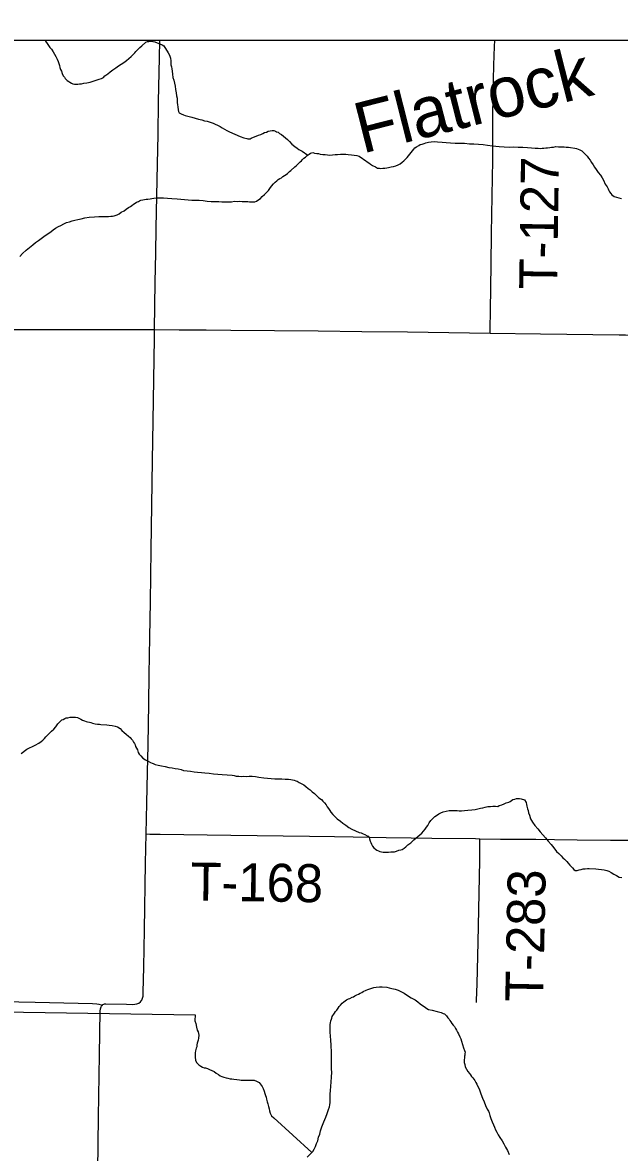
# Model space of a CAD drawing. Extents: x 2.1 to 73.9, y 4 to 26.
# Drawn here: x 44.468 to 44.915, y 18.709 to 19.554 of the extents above; entities that cross this region are included whole.
import ezdxf

# ---------------------------------------------------------------- set-up
doc = ezdxf.new("R2010")
doc.units = 0
for name, color, linetype in [('GM_X_County_Road', 7, 'Continuous'), ('GM_X_Minor_Lake_Text', 7, 'Continuous'), ('GM_X_Minor_River', 7, 'Continuous'), ('GM_X_Township_Road', 7, 'Continuous'), ('GM_X_Township_Road_Text', 7, 'Continuous'), ('SH_Text', 7, 'Continuous')]:
    doc.layers.add(name, color=color, linetype=linetype)

msp = doc.modelspace()

# ---------------------------------------------------------------- linework, layer by layer
at = {"layer": 'GM_X_County_Road'}
for points in [[(44.56658, 19.3248), (44.56701, 19.36025), (44.56761, 19.382), (44.56786, 19.40064), (44.56881, 19.44881), (44.56918, 19.47056), (44.56955, 19.49542), (44.57019, 19.52805), (44.57042, 19.54109)], [(44.56027, 18.94717), (44.56073, 18.97025), (44.56132, 18.99356), (44.56168, 19.01375), (44.56227, 19.04483), (44.56263, 19.06658), (44.56308, 19.09455), (44.56349, 19.12096), (44.56401, 19.15981), (44.56508, 19.22662), (44.56552, 19.25614), (44.56649, 19.3183), (44.56658, 19.3248)], [(44.55035, 18.81959), (44.55191, 18.81972), (44.55342, 18.82004), (44.55483, 18.82066), (44.55606, 18.82159), (44.55661, 18.82219), (44.55699, 18.82282), (44.55761, 18.82425), (44.55794, 18.82577), (44.55816, 18.82887), (44.55848, 18.84751), (44.55903, 18.87548), (44.55984, 18.9252), (44.56027, 18.94717)], [(44.51978, 18.31658), (44.52008, 18.34537), (44.52022, 18.37179), (44.5205, 18.39354), (44.52092, 18.43238), (44.52118, 18.44792), (44.5214, 18.46967), (44.52162, 18.48832), (44.52216, 18.51628), (44.52264, 18.54269), (44.52329, 18.60795), (44.52346, 18.62815), (44.52406, 18.69497), (44.52455, 18.73537), (44.52534, 18.78198), (44.52599, 18.81463), (44.52616, 18.81619), (44.52655, 18.8177), (44.52684, 18.81833), (44.52751, 18.81903)], [(44.52751, 18.81903), (44.52792, 18.81948), (44.5286, 18.81981), (44.5291, 18.81993), (44.53014, 18.82004), (44.54568, 18.81967), (44.55035, 18.81959)]]:
    msp.add_lwpolyline(points, dxfattribs=at)
at = {"layer": 'GM_X_Minor_River'}
for points in [[(44.48463, 19.54109), (44.48497, 19.54049), (44.48608, 19.53895), (44.48719, 19.5374), (44.4881, 19.53586), (44.4894, 19.5345), (44.49069, 19.53257), (44.4916, 19.53084), (44.4927, 19.52911), (44.49361, 19.52719), (44.49433, 19.52546), (44.49505, 19.52393), (44.4954, 19.5224), (44.49574, 19.52088), (44.49628, 19.51934), (44.49682, 19.518), (44.49754, 19.51628), (44.49826, 19.51455), (44.49919, 19.51358), (44.49974, 19.51262), (44.50122, 19.51107), (44.50441, 19.5091), (44.50535, 19.50869), (44.50668, 19.50847), (44.50763, 19.50845), (44.50915, 19.50842), (44.51029, 19.50858), (44.51182, 19.50874), (44.51353, 19.50908), (44.51601, 19.5094), (44.5185, 19.50992), (44.5206, 19.51063), (44.5229, 19.51134), (44.52501, 19.51205), (44.52692, 19.51258), (44.52827, 19.51331), (44.52944, 19.51461), (44.53156, 19.51608), (44.53331, 19.51756), (44.53544, 19.51922), (44.53756, 19.52069), (44.53969, 19.52216), (44.54162, 19.52345), (44.54355, 19.52473), (44.54548, 19.52621), (44.54742, 19.52769), (44.54897, 19.52917), (44.55033, 19.53047), (44.5517, 19.53196), (44.55267, 19.53289), (44.55403, 19.53437), (44.55559, 19.53586), (44.55695, 19.53716), (44.56005, 19.53975), (44.56139, 19.54028), (44.56235, 19.54045), (44.5633, 19.54062), (44.56444, 19.5406), (44.56539, 19.54039), (44.56671, 19.53998), (44.56859, 19.53936), (44.57048, 19.53856), (44.57217, 19.53776), (44.57348, 19.53697)], [(44.57348, 19.53697), (44.57679, 19.53196), (44.5777, 19.53004), (44.57841, 19.52794), (44.57874, 19.52584), (44.57871, 19.52432), (44.57886, 19.5228), (44.57921, 19.52146), (44.57955, 19.51975), (44.57971, 19.51803), (44.58004, 19.51594), (44.58036, 19.51346), (44.58107, 19.51136), (44.58141, 19.50926), (44.58192, 19.50697), (44.58225, 19.50449), (44.58276, 19.50201), (44.58309, 19.49973), (44.58342, 19.49782), (44.58358, 19.49611), (44.58354, 19.49459), (44.58369, 19.49287), (44.58404, 19.49135), (44.58437, 19.48906), (44.58453, 19.48792), (44.58508, 19.48696), (44.58639, 19.48617), (44.58827, 19.48536), (44.5896, 19.48496), (44.59148, 19.48434), (44.59451, 19.48371), (44.59696, 19.48289), (44.59942, 19.48226), (44.60188, 19.48164), (44.60395, 19.48102), (44.60585, 19.4806), (44.60755, 19.48018), (44.60905, 19.47958), (44.61057, 19.47917), (44.61207, 19.47837), (44.61358, 19.47777), (44.61564, 19.47677), (44.61714, 19.47579), (44.61883, 19.4748), (44.62071, 19.47381), (44.62278, 19.47281), (44.63068, 19.46922), (44.63351, 19.4682), (44.63559, 19.46778), (44.63653, 19.46757), (44.63805, 19.46753), (44.63901, 19.46789), (44.64075, 19.4688), (44.64266, 19.46952), (44.64439, 19.47024), (44.64611, 19.47077), (44.64765, 19.47149), (44.649, 19.47222), (44.65034, 19.47257), (44.65168, 19.47311), (44.65302, 19.47346), (44.65473, 19.47361), (44.65587, 19.47359), (44.657, 19.47318), (44.65795, 19.47278), (44.65908, 19.47237), (44.6602, 19.47159), (44.66151, 19.47061), (44.663, 19.46944), (44.6645, 19.46827), (44.66618, 19.4669), (44.66767, 19.46553), (44.66933, 19.46341), (44.67157, 19.46165), (44.67325, 19.46047), (44.67456, 19.45949), (44.67569, 19.4589), (44.67701, 19.4583), (44.68136, 19.45534)], [(44.74901, 19.44813), (44.75036, 19.44886), (44.75191, 19.44996), (44.75326, 19.45107), (44.75443, 19.45219), (44.7556, 19.45349), (44.75658, 19.4548), (44.75775, 19.4561), (44.76068, 19.45964), (44.76147, 19.46076), (44.76263, 19.4615), (44.76436, 19.4626), (44.76532, 19.46314), (44.76685, 19.46349), (44.76839, 19.46403), (44.76973, 19.46437), (44.77164, 19.4649), (44.77355, 19.46524), (44.77583, 19.46538), (44.7783, 19.46532), (44.78191, 19.46505), (44.78475, 19.4648), (44.78817, 19.46453), (44.79158, 19.46426), (44.795, 19.46419), (44.79862, 19.46411), (44.80222, 19.46383), (44.80564, 19.46376), (44.80906, 19.46349), (44.81247, 19.46322), (44.81588, 19.46277), (44.81949, 19.46231), (44.82461, 19.46181), (44.8284, 19.46153), (44.83201, 19.46126), (44.83543, 19.46138), (44.83885, 19.4613), (44.84227, 19.46122), (44.84569, 19.46096), (44.84872, 19.4607), (44.85157, 19.46044), (44.85385, 19.46039), (44.85537, 19.46036), (44.85671, 19.46052), (44.85803, 19.46049), (44.85937, 19.46065), (44.8607, 19.46081), (44.86242, 19.46096), (44.86375, 19.46112), (44.86528, 19.46127), (44.86699, 19.46162), (44.86908, 19.46157), (44.87117, 19.46152), (44.87308, 19.46148), (44.87478, 19.46125), (44.87649, 19.46121), (44.87782, 19.46099), (44.88123, 19.46054), (44.88236, 19.46013), (44.88368, 19.45972), (44.885, 19.45912), (44.88632, 19.45852), (44.88743, 19.45755), (44.88873, 19.45619), (44.8904, 19.45444), (44.89151, 19.45309), (44.89262, 19.45154), (44.89372, 19.44981), (44.89482, 19.44808), (44.89592, 19.44634), (44.89721, 19.44441), (44.89868, 19.44229), (44.90034, 19.44016), (44.90163, 19.43824), (44.90273, 19.4365), (44.904, 19.43363), (44.90528, 19.43151), (44.90619, 19.42997), (44.90655, 19.42882), (44.9071, 19.42786), (44.90802, 19.42651), (44.90894, 19.42554), (44.91063, 19.42436), (44.91233, 19.42375), (44.91403, 19.42334), (44.91611, 19.42291)], [(44.57336, 19.42341), (44.57621, 19.42316), (44.57944, 19.42289), (44.58342, 19.42261), (44.59177, 19.42186), (44.59442, 19.42161), (44.59708, 19.42155), (44.59994, 19.42148), (44.60297, 19.42122), (44.606, 19.42078), (44.60904, 19.42052), (44.6117, 19.42046), (44.61474, 19.42058), (44.61702, 19.42034), (44.6193, 19.42029), (44.62177, 19.42023), (44.62424, 19.42036), (44.62634, 19.4207), (44.62862, 19.42065), (44.63053, 19.42079), (44.63223, 19.42056), (44.63375, 19.42053), (44.63528, 19.42069), (44.63641, 19.42047), (44.63774, 19.42044), (44.63907, 19.42041), (44.6404, 19.42038), (44.64154, 19.42035), (44.64288, 19.4207), (44.64462, 19.42199), (44.64578, 19.42292), (44.64714, 19.42422), (44.64889, 19.42589), (44.65045, 19.42737), (44.65181, 19.42886), (44.65299, 19.43035), (44.65416, 19.43203), (44.65553, 19.43371), (44.65689, 19.43501), (44.65806, 19.43612), (44.65922, 19.43705), (44.66038, 19.43778), (44.66153, 19.43833), (44.6625, 19.43925), (44.66385, 19.43998), (44.66501, 19.44072), (44.66598, 19.44145), (44.66753, 19.44294), (44.6685, 19.44387), (44.6716, 19.44645), (44.67257, 19.44738), (44.67393, 19.44849), (44.67471, 19.44942), (44.67549, 19.45036), (44.67646, 19.45109), (44.67743, 19.45202), (44.6784, 19.45295), (44.67956, 19.45368), (44.68092, 19.45498), (44.68228, 19.45609), (44.68344, 19.45682), (44.68515, 19.45716), (44.68629, 19.45676), (44.68799, 19.45653), (44.68932, 19.4565), (44.69045, 19.4561), (44.69254, 19.45586), (44.69424, 19.45563), (44.69614, 19.45559), (44.69785, 19.45536), (44.69975, 19.45551), (44.70166, 19.45565), (44.70356, 19.4558), (44.70566, 19.45594), (44.70775, 19.45609), (44.70965, 19.45604), (44.71155, 19.45581), (44.71401, 19.45557), (44.7161, 19.45533), (44.71799, 19.4551), (44.71969, 19.45449), (44.72082, 19.4537), (44.72194, 19.45292), (44.72325, 19.45213), (44.72437, 19.45115), (44.72568, 19.45036), (44.72699, 19.44939), (44.7283, 19.44841), (44.7298, 19.44742), (44.73187, 19.44643), (44.73356, 19.44563), (44.73507, 19.44541), (44.73602, 19.44538), (44.73736, 19.44554), (44.73888, 19.44551), (44.7404, 19.44567), (44.74174, 19.44602), (44.74365, 19.44654), (44.74556, 19.44688), (44.74709, 19.44722), (44.74901, 19.44813)], [(44.46572, 19.3795), (44.46785, 19.38154), (44.47058, 19.38413), (44.47309, 19.38617), (44.47542, 19.3882), (44.47755, 19.38987), (44.47967, 19.39134), (44.4818, 19.39281), (44.48373, 19.39428), (44.48914, 19.39815), (44.49069, 19.39925), (44.49243, 19.40073), (44.49474, 19.40182), (44.49647, 19.40273), (44.49859, 19.40382), (44.5007, 19.40473), (44.50281, 19.40544), (44.50492, 19.40615), (44.50682, 19.40649), (44.50912, 19.40701), (44.5116, 19.40771), (44.51447, 19.4084), (44.51752, 19.40891), (44.52171, 19.40919), (44.52476, 19.40931), (44.52742, 19.40944), (44.53008, 19.40938), (44.53217, 19.40933), (44.53389, 19.40949), (44.53522, 19.40965), (44.53636, 19.40981), (44.53848, 19.41071), (44.54001, 19.41125), (44.54156, 19.41254), (44.54387, 19.41363), (44.54541, 19.41473), (44.54696, 19.41603), (44.5485, 19.41694), (44.54966, 19.41768), (44.55082, 19.4186), (44.55198, 19.41933), (44.55314, 19.42007), (44.55448, 19.42061), (44.55544, 19.42115), (44.5564, 19.42151), (44.55793, 19.42186), (44.55908, 19.42202), (44.56022, 19.42238), (44.56155, 19.42235), (44.56327, 19.4225), (44.56461, 19.42285), (44.56613, 19.423), (44.56823, 19.42334), (44.5707, 19.42328), (44.57336, 19.42341)], [(44.46678, 19.00741), (44.47103, 19.01054), (44.47719, 19.01363), (44.47988, 19.01509), (44.48162, 19.01638), (44.48298, 19.01749), (44.48414, 19.01861), (44.48531, 19.01991), (44.48648, 19.02121), (44.48785, 19.0227), (44.4894, 19.02418), (44.49115, 19.02566), (44.49271, 19.02734), (44.49409, 19.02959), (44.49584, 19.03126), (44.4972, 19.03256), (44.49815, 19.03291), (44.49931, 19.03365), (44.50046, 19.034), (44.5016, 19.03417), (44.50332, 19.03451), (44.50542, 19.03465), (44.50732, 19.03461), (44.50902, 19.03438), (44.51034, 19.03359), (44.51128, 19.03319), (44.51259, 19.0324), (44.5141, 19.0318), (44.51542, 19.03139), (44.51636, 19.03117), (44.51788, 19.03076), (44.51882, 19.03055), (44.52014, 19.03014), (44.52222, 19.02971), (44.52393, 19.02948), (44.52545, 19.02926), (44.52639, 19.02905), (44.53076, 19.02876), (44.53266, 19.02872)], [(44.53266, 19.02872), (44.53474, 19.02848), (44.53701, 19.02786), (44.5389, 19.02725), (44.54077, 19.02607), (44.54207, 19.02471), (44.54375, 19.02315), (44.54543, 19.02178), (44.54711, 19.02042), (44.54823, 19.01944), (44.54915, 19.01847), (44.55008, 19.01731), (44.55081, 19.01596), (44.55155, 19.015), (44.55209, 19.01385), (44.55244, 19.0127), (44.55299, 19.01136), (44.55372, 19.0102), (44.55408, 19.00924), (44.55443, 19.0081), (44.55517, 19.00694), (44.55628, 19.00558), (44.55776, 19.00403), (44.55982, 19.00266), (44.56189, 19.00166), (44.56358, 19.00067), (44.56471, 19.00027), (44.56565, 18.99986), (44.56716, 18.99926), (44.56924, 18.99864), (44.5717, 18.99821), (44.57454, 18.99758), (44.57737, 18.99694), (44.57984, 18.9967), (44.58192, 18.99627), (44.58419, 18.99584), (44.58646, 18.99541), (44.58835, 18.9948), (44.591, 18.99436), (44.59347, 18.99411), (44.59612, 18.99367), (44.59877, 18.99342), (44.60162, 18.99317), (44.60428, 18.99292), (44.6075, 18.99266), (44.61072, 18.9922), (44.61395, 18.99194), (44.61717, 18.99168), (44.62458, 18.99113), (44.62609, 18.99091), (44.62779, 18.99049), (44.62969, 18.99045), (44.63178, 18.99021), (44.63349, 18.99036), (44.63558, 18.99031), (44.63749, 18.99046), (44.63977, 18.99041), (44.64204, 18.99017), (44.64469, 18.98973), (44.64849, 18.98926), (44.65114, 18.98901), (44.65399, 18.98876), (44.65664, 18.98851), (44.6593, 18.98845), (44.66177, 18.98839), (44.66443, 18.98815), (44.6669, 18.98809), (44.6686, 18.98786), (44.66993, 18.98764), (44.67107, 18.98743), (44.67239, 18.98702), (44.67333, 18.98662), (44.67483, 18.98582), (44.67634, 18.98503), (44.67821, 18.98385), (44.67989, 18.98267), (44.68157, 18.9813), (44.68307, 18.98013), (44.68456, 18.97877), (44.68624, 18.9774), (44.68792, 18.97603), (44.68959, 18.97428), (44.69146, 18.97291), (44.69257, 18.97175), (44.69369, 18.97058), (44.69498, 18.96903), (44.6959, 18.9675), (44.69682, 18.96614), (44.69774, 18.96479), (44.69866, 18.96344), (44.70014, 18.9617), (44.70163, 18.96015), (44.7033, 18.95859), (44.70573, 18.95664), (44.7076, 18.95527), (44.70966, 18.9537), (44.7119, 18.95213), (44.71415, 18.95075), (44.7198, 18.94834), (44.72131, 18.94793), (44.72263, 18.94733)], [(44.72263, 18.94733), (44.72394, 18.94673), (44.72563, 18.94574), (44.72658, 18.94553), (44.72713, 18.94457), (44.72748, 18.94342), (44.72802, 18.94189), (44.72856, 18.94074), (44.72892, 18.93959), (44.72983, 18.93805), (44.73076, 18.93689), (44.73188, 18.93592), (44.733, 18.93513), (44.73412, 18.93454), (44.73525, 18.93394), (44.73639, 18.93373), (44.73771, 18.93351), (44.73923, 18.93347), (44.74056, 18.93344), (44.74171, 18.93361), (44.74342, 18.93376), (44.74609, 18.93389), (44.74762, 18.93442), (44.74934, 18.93495), (44.75087, 18.9353), (44.75183, 18.93566), (44.75337, 18.93657), (44.75472, 18.93749), (44.75628, 18.93898), (44.75841, 18.94064), (44.76073, 18.94268), (44.76674, 18.94786), (44.76792, 18.94935), (44.76909, 18.95084), (44.77007, 18.95215), (44.77125, 18.95364), (44.77224, 18.95552), (44.77342, 18.9572), (44.77478, 18.95869), (44.77634, 18.96018), (44.77769, 18.9611), (44.77942, 18.9622), (44.78096, 18.96292), (44.78269, 18.96364), (44.78498, 18.96435), (44.78708, 18.96468), (44.78842, 18.96484), (44.78975, 18.96481), (44.79127, 18.96478), (44.79298, 18.96474), (44.79468, 18.96451), (44.79639, 18.96447), (44.79868, 18.9648), (44.80116, 18.96494), (44.80401, 18.96525), (44.80649, 18.96558), (44.80859, 18.96591), (44.8105, 18.96644), (44.81222, 18.96678), (44.81414, 18.9673), (44.81605, 18.96764), (44.81795, 18.96779), (44.81985, 18.96794), (44.82175, 18.96789), (44.82346, 18.96785), (44.82462, 18.9684), (44.82653, 18.96911), (44.82826, 18.96965), (44.82979, 18.97037), (44.83171, 18.9709), (44.83286, 18.97144), (44.83479, 18.97292), (44.83632, 18.97326), (44.83747, 18.97362), (44.83862, 18.97378), (44.83976, 18.97376), (44.84108, 18.97354), (44.84353, 18.97272), (44.84463, 18.9708), (44.84498, 18.96927), (44.84533, 18.96793), (44.8455, 18.96698), (44.84585, 18.96602), (44.8462, 18.96468), (44.84655, 18.96297), (44.84727, 18.96124), (44.84797, 18.95857), (44.84943, 18.95606), (44.85128, 18.95355), (44.8535, 18.95103), (44.85535, 18.94871), (44.8572, 18.94658), (44.85924, 18.94426), (44.86127, 18.94174), (44.8635, 18.93922), (44.86553, 18.93671), (44.86756, 18.934), (44.86924, 18.93245), (44.87091, 18.9307), (44.87221, 18.92934), (44.87333, 18.92837)], [(44.87333, 18.92837), (44.87426, 18.92759), (44.87519, 18.92662), (44.8763, 18.92526), (44.87741, 18.92391), (44.87853, 18.92274), (44.87945, 18.92177), (44.88038, 18.92061), (44.8815, 18.91983), (44.88302, 18.91979), (44.88436, 18.92033), (44.88589, 18.92068), (44.88742, 18.92102), (44.88895, 18.92118), (44.89066, 18.92133), (44.89199, 18.9213), (44.89693, 18.921), (44.89901, 18.92076), (44.9011, 18.92052), (44.90318, 18.92029), (44.90507, 18.91987), (44.90658, 18.91926), (44.90827, 18.91827), (44.91033, 18.91709), (44.9124, 18.91609), (44.91447, 18.91491), (44.91636, 18.91448)], [(44.68086, 18.70534), (44.68495, 18.70962), (44.68613, 18.7113), (44.68712, 18.71318), (44.68793, 18.71544), (44.68874, 18.71751), (44.68937, 18.72016), (44.69018, 18.72242), (44.69081, 18.72487), (44.69183, 18.72808), (44.69325, 18.73184), (44.69484, 18.73523), (44.69586, 18.73805), (44.69688, 18.74107), (44.69749, 18.74296), (44.69771, 18.74447), (44.69794, 18.74617), (44.69798, 18.74788), (44.69803, 18.74997), (44.69808, 18.75244), (44.69833, 18.75509), (44.69859, 18.75812), (44.69886, 18.76154), (44.69894, 18.76514), (44.69921, 18.76894), (44.69908, 18.77122), (44.69894, 18.77369), (44.69899, 18.77597), (44.69905, 18.77844), (44.69911, 18.7811), (44.69897, 18.78338), (44.69902, 18.78547), (44.69887, 18.78737), (44.6989, 18.78889), (44.69874, 18.79022), (44.69859, 18.79193), (44.69844, 18.79365), (44.69828, 18.79498), (44.6983, 18.79593), (44.69832, 18.79688), (44.69815, 18.79783), (44.69799, 18.79879), (44.69802, 18.80011), (44.69805, 18.80144), (44.69808, 18.80296), (44.69811, 18.80448), (44.69833, 18.80581), (44.69856, 18.80732), (44.69896, 18.80845), (44.69937, 18.80939), (44.69958, 18.81053), (44.70135, 18.81296), (44.70214, 18.81427), (44.70311, 18.81538), (44.70409, 18.81669), (44.70488, 18.818), (44.70586, 18.81912), (44.70703, 18.82042), (44.70819, 18.82154), (44.70916, 18.82228), (44.71032, 18.82301), (44.71167, 18.82374), (44.71281, 18.82409), (44.71455, 18.825), (44.7155, 18.82536), (44.71647, 18.8261), (44.71801, 18.82683), (44.71935, 18.82737), (44.72051, 18.8281), (44.72166, 18.82864), (44.72281, 18.82919), (44.72493, 18.83028), (44.72627, 18.83082), (44.72762, 18.83136), (44.73068, 18.83224), (44.73258, 18.83258), (44.73487, 18.83271), (44.73696, 18.83267), (44.74038, 18.8324), (44.74227, 18.83198), (44.74416, 18.83156), (44.74681, 18.83112), (44.74888, 18.83031), (44.75095, 18.82931), (44.7534, 18.82812), (44.75583, 18.82636), (44.75864, 18.82458), (44.76164, 18.823), (44.7637, 18.82162), (44.76538, 18.82006), (44.7695, 18.81731), (44.77043, 18.81653), (44.77175, 18.81574), (44.7744, 18.8153), (44.77818, 18.81427), (44.78101, 18.81344), (44.78271, 18.81284)], [(43.5373, 18.82828), (44.59696, 18.81169)], [(44.59696, 18.81169), (44.59685, 18.80733), (44.59738, 18.80523), (44.59808, 18.80255), (44.5986, 18.80045), (44.59914, 18.79911), (44.59949, 18.79777), (44.59966, 18.79663), (44.59941, 18.79436), (44.59919, 18.79284), (44.59857, 18.79058), (44.59835, 18.78944), (44.59812, 18.78774), (44.59772, 18.7868), (44.59751, 18.78585), (44.5973, 18.78491), (44.59708, 18.78339), (44.59705, 18.78225), (44.59702, 18.78092), (44.59699, 18.77959), (44.59716, 18.77845), (44.59732, 18.7775), (44.59824, 18.77577), (44.59973, 18.7744), (44.60122, 18.77342), (44.60235, 18.77264), (44.60367, 18.77223), (44.60461, 18.77202), (44.60632, 18.7716), (44.60782, 18.77099), (44.60952, 18.7702), (44.61121, 18.7694), (44.6127, 18.76822), (44.61439, 18.76705), (44.6157, 18.76626), (44.61702, 18.76566), (44.61852, 18.76505), (44.62023, 18.76464), (44.62155, 18.76442), (44.62306, 18.764), (44.62439, 18.76378), (44.62591, 18.76356), (44.62818, 18.76332), (44.63008, 18.76309), (44.6314, 18.76287), (44.63292, 18.76283), (44.63464, 18.76298), (44.63616, 18.76295), (44.63749, 18.76292), (44.63863, 18.76289), (44.63996, 18.76286), (44.6411, 18.76284), (44.64279, 18.76204), (44.64392, 18.76163), (44.64486, 18.76104), (44.64726, 18.75814), (44.64799, 18.7566), (44.64852, 18.75469), (44.64905, 18.75297), (44.64958, 18.75144), (44.65012, 18.7501), (44.65047, 18.74857), (44.65081, 18.74666), (44.65134, 18.74513), (44.65187, 18.74322), (44.6524, 18.7415), (44.65275, 18.73997), (44.65309, 18.73826), (44.65364, 18.73729), (44.65419, 18.73633), (44.65586, 18.73459), (44.68421, 18.70884)], [(44.78271, 18.81284), (44.78365, 18.81243), (44.78514, 18.81107), (44.78605, 18.80953), (44.78717, 18.80856), (44.78772, 18.80759), (44.78827, 18.80663), (44.78919, 18.80528), (44.79011, 18.80412), (44.79104, 18.80296), (44.79196, 18.80161), (44.79269, 18.80027), (44.79342, 18.79892), (44.79415, 18.79757), (44.79505, 18.79546), (44.79577, 18.79374), (44.79631, 18.79221), (44.79701, 18.78953), (44.7979, 18.78704), (44.79862, 18.78513), (44.79898, 18.78398), (44.79895, 18.78284), (44.79873, 18.78171), (44.79871, 18.78076), (44.7985, 18.77962), (44.79846, 18.7781), (44.79844, 18.77715), (44.79842, 18.77601), (44.79877, 18.77468), (44.7991, 18.77277), (44.80001, 18.77104), (44.80112, 18.7693), (44.80223, 18.76795), (44.80315, 18.76679), (44.80389, 18.76563), (44.80481, 18.76466), (44.80629, 18.76254), (44.80702, 18.7612), (44.80794, 18.76003), (44.80993, 18.75562), (44.81082, 18.75275), (44.81208, 18.7495), (44.81334, 18.74662), (44.81442, 18.74394), (44.8155, 18.74125), (44.81661, 18.73971), (44.81715, 18.73837), (44.81749, 18.73646), (44.81819, 18.73416), (44.81928, 18.73167), (44.82018, 18.72956), (44.82109, 18.72764), (44.82181, 18.72572), (44.82291, 18.72399), (44.82382, 18.72207), (44.8251, 18.71995), (44.82675, 18.71745), (44.82803, 18.71533), (44.82931, 18.71283), (44.83077, 18.71014), (44.83204, 18.70726)]]:
    msp.add_lwpolyline(points, dxfattribs=at)
at = {"layer": 'GM_X_Township_Road'}
for points in [[(44.81777, 19.322), (44.81782, 19.32512), (44.81808, 19.33911), (44.81864, 19.3733), (44.8188, 19.39661), (44.81958, 19.43858), (44.81978, 19.45101), (44.81969, 19.4681), (44.81984, 19.4852), (44.82025, 19.51162), (44.82061, 19.52249), (44.82115, 19.53647), (44.82122, 19.54109)], [(44.31594, 19.32483), (44.33156, 19.32486), (44.3642, 19.32497), (44.39374, 19.32491), (44.43105, 19.32496), (44.45747, 19.3248), (44.56163, 19.32486), (44.56658, 19.3248)], [(44.56658, 19.3248), (44.58494, 19.32457), (44.60515, 19.32451), (44.6238, 19.32425), (44.68909, 19.32384), (44.72173, 19.32337), (44.75593, 19.32293), (44.81777, 19.322)], [(44.81777, 19.322), (44.85541, 19.32143), (44.91448, 19.32073), (44.91914, 19.32075), (44.93624, 19.3206), (44.97976, 19.31997), (45.01863, 19.31953), (45.03707, 19.3191), (45.0623, 19.31873), (45.06816, 19.31864)], [(44.56027, 18.94717), (44.563, 18.94713), (44.57076, 18.94702), (44.62358, 18.94628), (44.6826, 18.94545), (44.70124, 18.94518), (44.71522, 18.94495), (44.74007, 18.94463), (44.75871, 18.94427), (44.77424, 18.94413), (44.80686, 18.94371), (44.81003, 18.94366)], [(44.80766, 18.821), (44.80764, 18.82256), (44.80797, 18.83506), (44.80873, 18.86631), (44.81001, 18.92726), (44.81003, 18.93977), (44.81003, 18.94366)], [(44.81003, 18.94366), (44.82549, 18.9434), (44.85189, 18.9432), (44.86587, 18.943), (44.88295, 18.94269), (44.9078, 18.94243), (44.93265, 18.94249), (44.94197, 18.94253), (44.95595, 18.94245), (44.97303, 18.94228), (45.02274, 18.94172), (45.06158, 18.9414), (45.06299, 18.94139)], [(44.30668, 18.82454), (44.32026, 18.82437), (44.40421, 18.82287), (44.47728, 18.82134), (44.52003, 18.8203), (44.52336, 18.82014), (44.52498, 18.81984), (44.52668, 18.8193), (44.52751, 18.81903)]]:
    msp.add_lwpolyline(points, dxfattribs=at)
at = {"layer": 'SH_Text'}
msp.add_lwpolyline([(45.17346, 19.54109), (43.56201, 19.54109), (43.56201, 20.16526), (45.17346, 20.16526)], close=True, dxfattribs=at)

# ---------------------------------------------------------------- texts
at = {"layer": 'GM_X_Minor_Lake_Text'}
msp.add_text('Flatrock', height=0.037899, rotation=14.19873, dxfattribs=at).set_placement((44.72197, 19.45626))
at = {"layer": 'GM_X_Township_Road_Text'}
for s, rotation, p in [('T-127', 89.15733, (44.86787, 19.35456)), ('T-168', 359.15646, (44.59329, 18.89745)), ('T-283', 88.87128, (44.85746, 18.82119))]:
    msp.add_text(s, height=0.028409, rotation=rotation, dxfattribs=at).set_placement(p)

doc.saveas('drawing.dxf')
